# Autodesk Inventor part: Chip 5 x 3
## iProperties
Company: Autodesk Inc.
Created: 2005-12
Part Number: Chip 5 x 3
Document SubType Name: Modeling
Designer: Autodesk Inc.
Density: 1 g/cm^3
Author: Autodesk Inc.
Title: Personal Computer
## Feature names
1. Extrusion1
2. Extrusion2
3. Rectangular Pattern1
4. Mirror1
